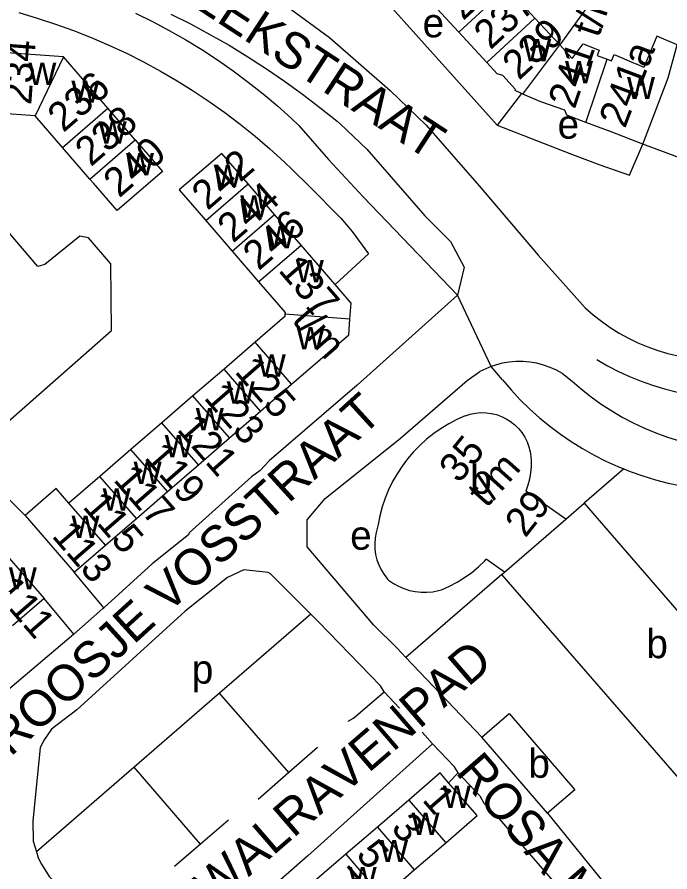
# Model space of a CAD drawing. Extents: x 159902 to 161769, y 383692 to 384875.
# Drawn here: x 160584.8 to 160675.1, y 384027.3 to 384145.4 of the extents above; entities that cross this region are included whole.
import ezdxf

# ---------------------------------------------------------------- set-up
doc = ezdxf.new("R2010")
doc.units = 0
for name, color, linetype in [('BLT_Basislijn', 7, 'Continuous'), ('BLT_Bebouwing', 7, 'Continuous'), ('BLT_Centroide', 7, 'Continuous'), ('BLT_Huisnummer', 7, 'Continuous'), ('BLT_Huisnummer_ tussenligend', 7, 'Continuous'), ('BLT_Huisnummer_reeks', 7, 'Continuous'), ('BLT_Onderverdeling_panden', 7, 'Continuous'), ('BLT_Straatnaam', 7, 'Continuous'), ('BLT_Vlakafsluiter', 7, 'Continuous')]:
    doc.layers.add(name, color=color, linetype=linetype)

msp = doc.modelspace()

# ---------------------------------------------------------------- linework, layer by layer
at = {"layer": 'BLT_Basislijn'}
for p, q in [((160654.56, 384134.88), (160651.22, 384130.47)), ((160623.75, 384130.46), (160627.85, 384125.75)), ((160629.48, 384130.69), (160633.16, 384127.16)), ((160622.89, 384124.33), (160625.2, 384122.07)), ((160663.36, 384105.24), (160656.87, 384112.5)), ((160631.85, 384094.53), (160645.73, 384106.97)), ((160651.93, 384095.27), (160650.37, 384097.12)), ((160660.25, 384096.17), (160661.59, 384095.12)), ((160668.72, 384082.97), (160663.23, 384078.23)), ((160596.79, 384063.78), (160592.69, 384068.69)), ((160651.87, 384068.39), (160638.58, 384056.91)), ((160592.64, 384060.12), (160588.54, 384065.04)), ((160625.43, 384062.88), (160612.8, 384051.95)), ((160626.5, 384061.81), (160625.43, 384062.88)), ((160638.58, 384056.91), (160649.08, 384045.9)), ((160637.69, 384049.9), (160635.59, 384052.15)), ((160612.8, 384051.95), (160600.98, 384041.72)), ((160622.4, 384041.01), (160612.8, 384051.95)), ((160640.82, 384046.56), (160642.26, 384044.96)), ((160626.35, 384044.48), (160622.4, 384041.01)), ((160600.98, 384041.72), (160587.47, 384030.02)), ((160610.18, 384031.09), (160600.98, 384041.72)), ((160622.4, 384041.01), (160618.14, 384037.25)), ((160644.49, 384039.59), (160645.82, 384040.97)), ((160614.03, 384034.4), (160610.18, 384031.09)), ((160658.18, 384035.37), (160667.52, 384023.83)), ((160610.18, 384031.09), (160606.56, 384027.99))]:
    msp.add_line(p, q, dxfattribs=at)
for points in [[(160668.63, 384153.77), (160659.85, 384141.58)], [(160611.94, 384153.07), (160621.97, 384147.01), (160628.03, 384142.61), (160636.39, 384135.29), (160641.4, 384130.48), (160648.72, 384122.12), (160656.87, 384112.5)], [(160651.22, 384130.47), (160635.51, 384148), (160632.01, 384152.57)], [(160585.02, 384146.04), (160587.57, 384145.29), (160590.1, 384144.47), (160592.59, 384143.57), (160595.06, 384142.59), (160597.5, 384141.54), (160599.91, 384140.42), (160602.28, 384139.23), (160604.62, 384137.96), (160606.92, 384136.63), (160609.17, 384135.23), (160611.38, 384133.76), (160613.55, 384132.22), (160615.67, 384130.62), (160617.74, 384128.96), (160619.76, 384127.23), (160621.72, 384125.44), (160622.89, 384124.33)], [(160601.19, 384145.97), (160603.54, 384144.82), (160605.85, 384143.59), (160608.12, 384142.3), (160610.35, 384140.94), (160612.54, 384139.51), (160614.68, 384138.01), (160616.77, 384136.45), (160618.82, 384134.82), (160620.82, 384133.14), (160622.76, 384131.39), (160623.75, 384130.46)], [(160606.07, 384145.85), (160608.79, 384144.48), (160611.47, 384143.04), (160614.12, 384141.53), (160616.72, 384139.94), (160619.28, 384138.29), (160621.79, 384136.58), (160624.26, 384134.79), (160626.68, 384132.95), (160629.06, 384131.04), (160629.48, 384130.69)], [(160651.22, 384130.47), (160661.27, 384126.59), (160665.4, 384125.01), (160669.49, 384123.59), (160671.37, 384127.88)], [(160633.16, 384127.16), (160641.2, 384117.95), (160644.75, 384114.39), (160646.63, 384110.84), (160645.73, 384106.97)], [(160627.85, 384125.75), (160632.65, 384120.58), (160645.73, 384106.97)], [(160625.2, 384122.07), (160629.56, 384117.63), (160631.15, 384115.78), (160633.39, 384112.69), (160628.78, 384108.44)], [(160585.91, 384076.54), (160578.09, 384084.32), (160578.09, 384084.74), (160597.85, 384102.11), (160597.75, 384111.32), (160594.69, 384114.92), (160593.48, 384115.14), (160588.64, 384111.22), (160587.65, 384110.93), (160583.44, 384115.94), (160580.8, 384118.74), (160580.32, 384118.93), (160560.65, 384120.34), (160558.3, 384120.35), (160557.69, 384120.18), (160555.62, 384118.2), (160552.47, 384072.33), (160552.47, 384071.77), (160553.15, 384071.33), (160555.77, 384068.67), (160556.14, 384067.93)], [(160663.36, 384105.24), (160664.46, 384104.27), (160665.62, 384103.37), (160666.82, 384102.53), (160668.07, 384101.75), (160669.35, 384101.04), (160670.68, 384100.41), (160672.03, 384099.84), (160673.41, 384099.36), (160674.82, 384098.94), (160676.25, 384098.61), (160677.7, 384098.35), (160679.15, 384098.18), (160680.62, 384098.08), (160682.09, 384098.06), (160683.55, 384098.12), (160685.01, 384098.27), (160686.46, 384098.49), (160687.9, 384098.79), (160689.32, 384099.17), (160690.71, 384099.62), (160692.08, 384100.15), (160693.42, 384100.76), (160693.93, 384101.01)], [(160665, 384098.1), (160666.47, 384097.24), (160667.98, 384096.45), (160669.52, 384095.74), (160671.1, 384095.1), (160672.7, 384094.53), (160674.33, 384094.04), (160675.97, 384093.62), (160677.64, 384093.29), (160679.32, 384093.03), (160681.01, 384092.85), (160682.71, 384092.75), (160684.41, 384092.73), (160686.11, 384092.8), (160687.8, 384092.94), (160689.49, 384093.16), (160690.56, 384093.34)], [(160650.37, 384097.12), (160650.07, 384097.01), (160649.2, 384096.63), (160648.81, 384096.43)], [(160660.25, 384096.17), (160659.4, 384096.62), (160658.53, 384097.01), (160657.62, 384097.33), (160656.69, 384097.57), (160655.74, 384097.73), (160654.78, 384097.8), (160653.82, 384097.8), (160652.86, 384097.73), (160651.91, 384097.57), (160650.98, 384097.33), (160650.37, 384097.12)], [(160634.16, 384061.38), (160624.9, 384072.18), (160624.9, 384075.94), (160627.4, 384078.87), (160637.85, 384087.23), (160647.05, 384095.17), (160648.81, 384096.43)], [(160631.85, 384094.53), (160619.65, 384084.07), (160618.43, 384082.76), (160617.24, 384081.89), (160608.59, 384074.12), (160608.53, 384073.87), (160603.48, 384069.83), (160596.79, 384063.78)], [(160651.93, 384095.27), (160653.12, 384093.88), (160654.38, 384092.54), (160655.69, 384091.26), (160657.05, 384090.04), (160658.47, 384088.88), (160659.94, 384087.78), (160661.45, 384086.74), (160663.01, 384085.77), (160664.61, 384084.88), (160666.24, 384084.05), (160667.91, 384083.29), (160668.72, 384082.97)], [(160661.59, 384095.12), (160662.88, 384094), (160664.21, 384092.93), (160665.6, 384091.93), (160667.04, 384090.99), (160668.51, 384090.12), (160670.03, 384089.32), (160671.58, 384088.59), (160673.16, 384087.94), (160674.77, 384087.36), (160676.41, 384086.86)], [(160668.72, 384082.97), (160669.61, 384082.61), (160671.34, 384082), (160673.1, 384081.47), (160674.87, 384081.01), (160676.67, 384080.64), (160678.47, 384080.34), (160680.3, 384080.12), (160682.12, 384079.98), (160683.96, 384079.92), (160685.79, 384079.94), (160687.62, 384080.04), (160689.44, 384080.22), (160691.26, 384080.48), (160693.06, 384080.82), (160694.85, 384081.24), (160696.61, 384081.73), (160698.35, 384082.3), (160700, 384082.92)], [(160625.43, 384062.88), (160619.84, 384068.48), (160619.52, 384068.67), (160616.18, 384069.02), (160613.88, 384067.97), (160608.05, 384063.29), (160593.07, 384049.65)], [(160592.64, 384060.12), (160596.66, 384063.66), (160596.79, 384063.78)], [(160635.59, 384052.15), (160635.05, 384052.98), (160626.5, 384061.81)], [(160634.16, 384061.38), (160637.37, 384058.19), (160638.58, 384056.91)], [(160592.64, 384060.12), (160592.26, 384059.78), (160583.51, 384052.39), (160567.19, 384037.86), (160565.76, 384036.84), (160563.32, 384035.66), (160561.13, 384034.92), (160554.58, 384034.83), (160545.94, 384035.22), (160527.14, 384036.5)], [(160630.58, 384048.09), (160631.34, 384048.49), (160635.59, 384052.15)], [(160593.07, 384049.65), (160589.56, 384046.97), (160588.45, 384045.38), (160587.97, 384044.42), (160586.96, 384034.32), (160587.01, 384031.51), (160587.47, 384030.02)], [(160642.26, 384044.96), (160625.02, 384029.48), (160603.61, 384010.75)], [(160645.82, 384040.97), (160645.32, 384041.79), (160642.26, 384044.96)], [(160645.82, 384040.97), (160648.81, 384037.79), (160649.38, 384036.74), (160651.47, 384034.58), (160659.77, 384024.99)], [(160587.47, 384030.02), (160587.72, 384029.19), (160588.18, 384028.33)], [(160588.18, 384028.33), (160589.24, 384026.64), (160591.17, 384024.76), (160596.36, 384018.91)]]:
    msp.add_lwpolyline(points, dxfattribs=at)
at = {"layer": 'BLT_Bebouwing'}
for p, q in [((160645.89, 384143.33), (160642.26, 384147.26)), ((160656.43, 384145.29), (160659.85, 384141.58)), ((160649.77, 384139.14), (160645.89, 384143.33)), ((160591.23, 384139.92), (160582.11, 384140.58)), ((160597.34, 384132.83), (160591.23, 384139.92)), ((160654.76, 384134.79), (160654.56, 384134.88)), ((160601.12, 384128.46), (160597.34, 384132.83)), ((160587.29, 384131.78), (160581.51, 384132.2)), ((160591.07, 384127.41), (160587.29, 384131.78)), ((160666.96, 384129.55), (160663.47, 384130.87)), ((160671.37, 384127.88), (160666.96, 384129.55)), ((160676.95, 384125.77), (160671.37, 384127.88)), ((160594.84, 384123.04), (160591.07, 384127.41)), ((160620.42, 384118.12), (160616.76, 384122.36)), ((160610.9, 384117.29), (160614.55, 384113.05)), ((160624.08, 384113.89), (160620.42, 384118.12)), ((160628.78, 384108.44), (160624.08, 384113.89)), ((160614.55, 384113.05), (160618.21, 384108.82)), ((160617.71, 384100.47), (160613.42, 384096.76)), ((160613.42, 384096.76), (160609.13, 384093.05)), ((160618.48, 384090.96), (160622.77, 384094.67)), ((160609.13, 384093.05), (160604.84, 384089.34)), ((160614.19, 384087.25), (160618.48, 384090.96)), ((160604.84, 384089.34), (160600.54, 384085.64)), ((160609.9, 384083.55), (160614.19, 384087.25)), ((160600.54, 384085.64), (160596.25, 384081.93)), ((160605.6, 384079.84), (160609.9, 384083.55)), ((160596.25, 384081.93), (160591.96, 384078.22)), ((160601.31, 384076.13), (160605.6, 384079.84)), ((160660.69, 384076.03), (160655.16, 384079.9)), ((160660.69, 384076.03), (160663.23, 384078.23)), ((160585.91, 384076.54), (160592.69, 384068.69)), ((160597.02, 384072.42), (160601.31, 384076.13)), ((160592.69, 384068.69), (160597.02, 384072.42)), ((160583.12, 384071.32), (160588.54, 384065.04)), ((160652.21, 384068.68), (160649.7, 384070.48)), ((160651.87, 384068.39), (160652.21, 384068.68)), ((160679.44, 384036.6), (160651.87, 384068.39)), ((160588.54, 384065.04), (160584.18, 384061.28)), ((160658.18, 384035.37), (160649.08, 384045.9)), ((160638.97, 384037.2), (160634.63, 384033.45)), ((160634.63, 384033.45), (160630.29, 384029.71)), ((160639.74, 384027.54), (160644.08, 384031.29)), ((160630.29, 384029.71), (160625.95, 384025.96)), ((160635.4, 384023.79), (160639.74, 384027.54))]:
    msp.add_line(p, q, dxfattribs=at)
for points in [[(160655.24, 384151.98), (160657.09, 384149.98), (160654.39, 384147.49), (160656.43, 384145.29)], [(160676.08, 384141.61), (160673.3, 384142.8), (160671.51, 384138.48), (160670.5, 384138.91)], [(160659.85, 384141.58), (160661.59, 384139.7), (160663.09, 384141.71), (160665.3, 384140.87), (160665.03, 384140.13), (160666.41, 384139.61)], [(160666.41, 384139.61), (160667.03, 384139.38), (160667.4, 384140.24), (160670.05, 384139.1), (160670.5, 384138.91)], [(160654.56, 384134.88), (160653.69, 384135.26), (160653.76, 384135.43), (160651.97, 384137.36), (160651.19, 384137.6), (160649.77, 384139.14)], [(160663.47, 384130.87), (160660.86, 384131.86), (160660.54, 384132.58), (160657.26, 384133.7), (160654.76, 384134.79)], [(160601.12, 384128.46), (160604.89, 384124.09), (160598.62, 384118.67), (160595.35, 384122.46), (160594.84, 384123.04)], [(160616.76, 384122.36), (160613.1, 384126.59), (160607.24, 384121.53), (160610.9, 384117.29)], [(160618.21, 384108.82), (160621.87, 384104.58), (160621.85, 384104.34)], [(160630.84, 384103.68), (160631, 384105.86), (160628.78, 384108.44)], [(160621.85, 384104.34), (160621.83, 384104.02), (160617.71, 384100.47)], [(160622.77, 384094.67), (160630.68, 384101.5), (160630.84, 384103.68)], [(160646.79, 384090.31), (160645.64, 384089.8), (160644.52, 384089.22), (160643.45, 384088.57), (160642.42, 384087.85), (160641.43, 384087.06), (160640.5, 384086.22), (160639.62, 384085.31), (160638.8, 384084.36), (160638.04, 384083.35), (160637.35, 384082.3), (160636.73, 384081.21), (160636.18, 384080.07), (160635.7, 384078.91), (160635.29, 384077.72), (160634.97, 384076.5), (160634.72, 384075.27), (160634.66, 384074.91)], [(160646.79, 384090.31), (160647.49, 384090.54), (160648.2, 384090.68), (160648.93, 384090.75), (160649.66, 384090.74), (160650.39, 384090.65), (160651.1, 384090.48), (160651.79, 384090.23), (160652.45, 384089.91), (160653.06, 384089.52), (160653.64, 384089.07), (160654.15, 384088.55), (160654.61, 384087.98), (160655.01, 384087.37), (160655.33, 384086.71), (160655.58, 384086.03), (160655.76, 384085.32), (160655.8, 384085.08)], [(160655.8, 384085.08), (160655.89, 384084.2), (160655.9, 384083.31), (160655.83, 384082.43), (160655.68, 384081.55), (160655.45, 384080.7), (160655.16, 384079.9)], [(160591.96, 384078.22), (160590.19, 384080.24), (160585.91, 384076.54)], [(160663.23, 384078.23), (160684.68, 384053.47), (160687.42, 384053.09), (160700, 384060.86)], [(160634.66, 384074.91), (160634.45, 384074.18), (160634.31, 384073.43), (160634.26, 384072.67), (160634.29, 384071.9), (160634.39, 384071.15), (160634.57, 384070.4), (160634.83, 384069.69), (160635.17, 384069), (160635.57, 384068.35), (160636.04, 384067.75), (160636.18, 384067.59)], [(160643.5, 384066.24), (160644.61, 384066.75), (160645.68, 384067.32), (160646.7, 384067.96), (160647.69, 384068.67), (160648.62, 384069.44), (160649.5, 384070.28), (160649.7, 384070.48)], [(160636.18, 384067.59), (160636.85, 384067.13), (160637.56, 384066.74), (160638.31, 384066.42), (160639.08, 384066.18), (160639.88, 384066.01), (160640.68, 384065.92), (160641.49, 384065.91), (160642.3, 384065.99), (160643.1, 384066.14), (160643.5, 384066.24)], [(160649.08, 384045.9), (160652.86, 384049.16), (160661.94, 384038.59), (160658.18, 384035.37)], [(160644.49, 384039.59), (160643.31, 384040.95), (160638.97, 384037.2)], [(160644.08, 384031.29), (160648.42, 384035.04), (160644.49, 384039.59)]]:
    msp.add_lwpolyline(points, dxfattribs=at)
at = {"layer": 'BLT_Onderverdeling_panden'}
for p, q in [((160655.24, 384151.98), (160645.89, 384143.33)), ((160656.43, 384145.29), (160649.77, 384139.14)), ((160654.76, 384134.79), (160659.85, 384141.58)), ((160591.23, 384139.92), (160587.29, 384131.78)), ((160663.47, 384130.87), (160666.41, 384139.61)), ((160591.07, 384127.41), (160597.34, 384132.83)), ((160594.84, 384123.04), (160601.12, 384128.46)), ((160610.9, 384117.29), (160616.76, 384122.36)), ((160614.55, 384113.05), (160620.42, 384118.12)), ((160618.21, 384108.82), (160624.08, 384113.89)), ((160630.84, 384103.68), (160621.85, 384104.34)), ((160622.77, 384094.67), (160617.71, 384100.47)), ((160618.48, 384090.96), (160613.42, 384096.76)), ((160614.19, 384087.25), (160609.13, 384093.05)), ((160609.9, 384083.55), (160604.84, 384089.34)), ((160605.6, 384079.84), (160600.54, 384085.64)), ((160601.31, 384076.13), (160596.25, 384081.93)), ((160597.02, 384072.42), (160591.96, 384078.22)), ((160652.21, 384068.68), (160660.69, 384076.03)), ((160638.97, 384037.2), (160644.08, 384031.29)), ((160634.63, 384033.45), (160639.74, 384027.54)), ((160630.29, 384029.71), (160635.4, 384023.79))]:
    msp.add_line(p, q, dxfattribs=at)
msp.add_lwpolyline([(160671.37, 384127.88), (160674.86, 384137.04), (160676.08, 384141.61)], dxfattribs=at)
at = {"layer": 'BLT_Vlakafsluiter'}
msp.add_line((160650.37, 384097.12), (160645.73, 384106.97), dxfattribs=at)

# ---------------------------------------------------------------- texts
at = {"layer": 'BLT_Centroide'}
for s, p in [('e', (160640.89, 384142.63)), ('w', (160654.81, 384139.33)), ('w', (160586.36, 384136.06)), ('w', (160660.59, 384136.28)), ('w', (160669.16, 384134.09)), ('w', (160592.31, 384133.58)), ('e', (160659.56, 384128.62)), ('w', (160596.09, 384127.94)), ('w', (160599.87, 384123.56)), ('w', (160612, 384121.94)), ('w', (160615.66, 384117.72)), ('w', (160619.31, 384113.47)), ('w', (160623.36, 384108.78)), ('w', (160623.46, 384099.5)), ('w', (160618.09, 384095.72)), ('w', (160613.8, 384092)), ('w', (160609.52, 384088.31)), ('w', (160605.22, 384084.59)), ('w', (160600.92, 384080.88)), ('b', (160647.47, 384079.53)), ('w', (160596.64, 384077.19)), ('w', (160592.34, 384073.44)), ('e', (160630.87, 384071.8)), ('w', (160583.66, 384066.3)), ('b', (160671.84, 384056.81)), ('p', (160608.96, 384053.29)), ('b', (160655.52, 384040.27)), ('w', (160643.69, 384036.11)), ('w', (160639.36, 384032.38)), ('w', (160635.02, 384028.62)), ('w', (160630.67, 384024.88))]:
    msp.add_text(s, height=4, dxfattribs=at).set_placement(p)
at = {"layer": 'BLT_Huisnummer'}
for s, rotation, p in [('239', 42.7511, (160654.22, 384136.6)), ('234', 85.8541, (160586.75, 384133.22)), ('241a', 69.2736, (160668.89, 384129.92)), ('236', 40.8187, (160591.2, 384129.38)), ('240', 40.8146, (160598.92, 384120.34)), ('242', 40.8194, (160611.14, 384118.6)), ('246', 40.8194, (160618.22, 384110.28)), ('125', 311.1054, (160614.77, 384096.36)), ('121', 311.111, (160606.78, 384088.37)), ('117', 311.1054, (160598, 384081.4)), ('113', 310.8165, (160589.48, 384073.65)), ('111', 310.8165, (160581.52, 384065.98)), ('1', 310.8224, (160640.71, 384037.17)), ('5', 310.8176, (160631.55, 384029.56))]:
    msp.add_text(s, height=4, rotation=rotation, dxfattribs=at).set_placement(p)
at = {"layer": 'BLT_Huisnummer_ tussenligend'}
for s, rotation, p in [('235', 42.7524, (160646.49, 384144.85)), ('237', 42.7524, (160650.27, 384140.81)), ('238', 40.8187, (160595, 384124.65)), ('244', 40.8194, (160614.68, 384114.09)), ('123', 311.111, (160610.51, 384092.74)), ('119', 311.1054, (160602.27, 384084.48)), ('115', 310.8165, (160593.75, 384077.68)), ('3', 310.8224, (160636.39, 384033.24)), ('7', 310.8176, (160627.51, 384025.78))]:
    msp.add_text(s, height=4, rotation=rotation, dxfattribs=at).set_placement(p)
at = {"layer": 'BLT_Huisnummer_reeks'}
for s, rotation, p in [('241 t/m 241-03', 71.396, (160661.93, 384132.59)), ('137', 310.8156, (160620.82, 384110.37)), ('t/m', 311.1054, (160622.7, 384103.46)), ('35', 50.7585, (160645.93, 384080.84)), ('t/m', 48.2786, (160649.72, 384077.46)), ('29', 51.7901, (160655.1, 384073.33))]:
    msp.add_text(s, height=4, rotation=rotation, dxfattribs=at).set_placement(p)
at = {"layer": 'BLT_Straatnaam'}
for s, height, rotation, p in [('LIJMBEEKSTRAAT', 4.9999, 326.785, (160592.64, 384157.69)), ('ROOSJE VOSSTRAAT', 5, 42.3212, (160583.89, 384043.09)), ('ANNA WALRAVENPAD', 5, 40.8188, (160596.57, 384009.03)), ('ROSA MANUSSTRAAT', 5, 310.901, (160645.31, 384040.98))]:
    msp.add_text(s, height=height, rotation=rotation, dxfattribs=at).set_placement(p)

doc.saveas('drawing.dxf')
